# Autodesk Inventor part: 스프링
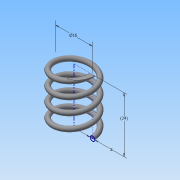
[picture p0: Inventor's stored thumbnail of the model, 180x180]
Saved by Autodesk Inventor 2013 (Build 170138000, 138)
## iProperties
Created: 2015-09
Part Number: 스프링
Material: 일반
Document SubType Name: Modeling
Designer: Administrator
Density: 1 g/cm^3
Author: Administrator
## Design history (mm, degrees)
sketch "스케치1"
  geometry: L1 (0, 0)-(8, 0); L2 (8, 0)-(8, 24); L3 (8, 24)-(0, 24); L4 (0, 24)-(0, 0); C1 r 1 at (8, 0)
  constraints: 8 end point, 2 parallel, 1 centre point, 1 coincident, 1 horizontal, 1 perpendicular
  dimensions: "d0" = 16 diameter of L2 L4; "d2" = 24 distance of L1.end L2.end (derived); "d3" = 2 diameter of C1
feature "코일1" sketch "스케치1" pitch "d4" = 10; turns "d6" = 4; dims "d5" = 24 (= d2), "d7" = 0, angle "d8" = 90 deg, angle "d9" = 90 deg, "d10" = 0, "d11" = 0
sketch "스케치2"
  geometry: L1 (-9, 0)-(-7, 0) reference; 1 further point
  constraints: 1 horizontal alignment
extrude "돌출1" cut sketch "스케치2" distance "d12" = 10; taper "d13" = 0 deg
node "작업 평면1"
sketch "스케치3"
  geometry: L1 (2, 0)-(0, 0) reference; 1 further point
  constraints: 1 horizontal alignment
extrude "돌출2" cut sketch "스케치3" distance "d14" = 10; taper "d15" = 0 deg
node "솔리드1"
node "절단 모서리 투영1"
node "절단 모서리 투영2"
